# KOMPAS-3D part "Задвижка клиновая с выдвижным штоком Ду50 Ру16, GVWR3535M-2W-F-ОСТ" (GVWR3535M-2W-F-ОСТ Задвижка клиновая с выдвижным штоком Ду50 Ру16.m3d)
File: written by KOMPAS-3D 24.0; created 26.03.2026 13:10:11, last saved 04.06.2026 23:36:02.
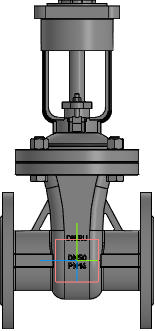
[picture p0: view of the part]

Document properties: Автор: R2D2; Полное имя файла: E:\Работа\Зайцев\GVWR3535M-2W-F-ОСТ Задвижка клиновая 30нж941нж DN.ru Ду50-200 Ру16\исходные данные\DN50\DN50\GVWR3535M-2W-F-ОСТ Задвижка клиновая с выдвижным штоком Ду50 Ру16.m3d

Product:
- Part/product: Задвижка клиновая с выдвижным штоком Ду50 Ру16  | designation GVWR3535M-2W-F-ОСТ
    Масса: 12
    Раздел спецификации: Прочие изделия
    Примечание: D040-08606

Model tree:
1. Операция без истории:1

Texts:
  GVWR3535M-2W-F-ОСТ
